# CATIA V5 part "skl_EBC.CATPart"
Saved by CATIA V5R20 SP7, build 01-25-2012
Part number: skl_EBC
Publications: "Axe_CBE_B", "Axe_CBE_C", "Axe_CBE_E", "CE", "BC", "EB", "PoinT B", "Point E", "Point C", "Plan.1"
Bounding box of the stored display mesh (mm): x -20 to 20, y -127.331 to -2.039, z 4.744 to 95.272
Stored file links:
  U:\IAO-Thinkmotion\TRAVAIL A RENDRE\skl_EBC.CATPart
  U:\IAO-Thinkmotion\TRAVAIL A RENDRE\skl_levier2bras.CATProduct
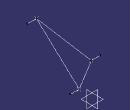
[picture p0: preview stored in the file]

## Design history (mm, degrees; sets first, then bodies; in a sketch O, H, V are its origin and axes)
Set1
  Point1 "PoinT B": linked copy from another document
  DatumPoint1 "Point E": linked copy from another document
  DatumPoint2 "Point C": linked copy from another document
  Plane1: linked copy from another document
Set2
  Line1 "EB": type PtPt, FirstPoint Point1, SecondPoint DatumPoint1
  Line2 "BC": type PtPt, FirstPoint Point1, SecondPoint DatumPoint2
  Line3 "CE": type PtPt, FirstPoint DatumPoint1, SecondPoint DatumPoint2
  Line4 "Axe_CBE_E": type Normal, RefPoint DatumPoint1, RefSkin Plane1, Start 0, End 20
  Line5 "Axe_CBE_C": type Normal, RefPoint DatumPoint2, RefSkin Plane1, Start 0, End 20
  Line6 "Axe_CBE_B": type Normal, RefPoint Point1, RefSkin Plane1, Start 0, End 20
Body1 (main body)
